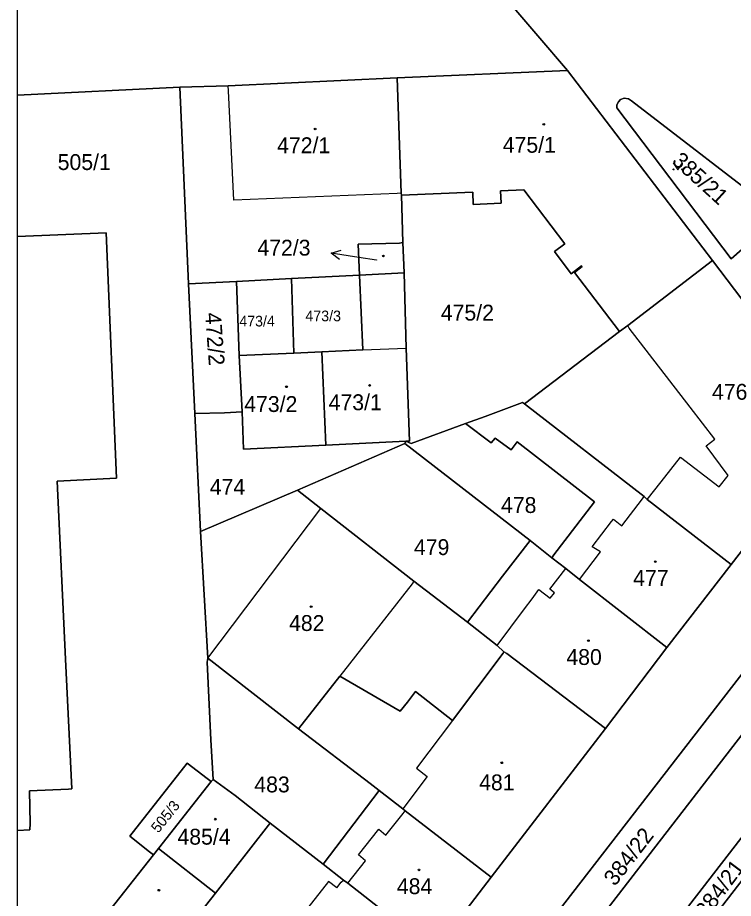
# Model space of a CAD drawing. Extents: x -598934 to -598196, y -1162208 to -1161502.
# Drawn here: x -598932 to -598855.4, y -1162110.9 to -1162016.6 of the extents above; entities that cross this region are included whole.
import ezdxf

# ---------------------------------------------------------------- set-up
doc = ezdxf.new("R2010")
doc.units = 0
for name, color, linetype in [('KN_CAR_KR', 7, 'Continuous'), ('KN_KULTURY', 7, 'Continuous'), ('KN_PARC_CIS_POM', 7, 'Continuous'), ('KN_PARC_CIS_POZ', 7, 'Continuous'), ('KN_PARC_CIS_STAV', 7, 'Continuous'), ('KN_PARC_PLOCHA', 7, 'Continuous'), ('PARC_C_SIPKA', 7, 'Continuous'), ('parcely_l', 7, 'Continuous')]:
    doc.layers.add(name, color=color, linetype=linetype)

msp = doc.modelspace()

# ---------------------------------------------------------------- linework, layer by layer
at = {"layer": 'KN_CAR_KR'}
for points in [[(-598909.44, -1162024.41), (-598909.46, -1162023.88)], [(-598908.86, -1162036.13), (-598909.44, -1162024.41)], [(-598891.37, -1162035.4), (-598908.86, -1162036.13)], [(-598890.96, -1162035.38), (-598891.37, -1162035.4)], [(-598866.55, -1162049.83), (-598866.7, -1162049.56)], [(-598860.03, -1162058.3), (-598866.55, -1162049.83)], [(-598895.07, -1162052.18), (-598890.43, -1162051.97)], [(-598857.38, -1162061.75), (-598860.03, -1162058.3)], [(-598858.3, -1162062.43), (-598857.38, -1162061.75)], [(-598855.94, -1162065.64), (-598858.3, -1162062.43)], [(-598863.13, -1162066.29), (-598861.06, -1162063.66)], [(-598861.06, -1162063.66), (-598856.91, -1162066.84)], [(-598856.91, -1162066.84), (-598855.94, -1162065.64)], [(-598864.6, -1162068.19), (-598863.13, -1162066.29)], [(-598865.12, -1162068.13), (-598864.95, -1162067.87)], [(-598867.33, -1162071.02), (-598865.12, -1162068.13)], [(-598911.67, -1162085.18), (-598899.56, -1162069.15)], [(-598870.52, -1162073.25), (-598868.43, -1162070.54)], [(-598868.43, -1162070.54), (-598868.23, -1162070.29)], [(-598868.23, -1162070.29), (-598867.33, -1162071.02)], [(-598869.61, -1162073.81), (-598870.52, -1162073.25)], [(-598871.87, -1162076.75), (-598869.61, -1162073.81)], [(-598875.04, -1162077.8), (-598873.32, -1162075.59)], [(-598889.78, -1162077.22), (-598897.51, -1162087.11)], [(-598889.59, -1162076.93), (-598889.78, -1162077.22)], [(-598876.92, -1162078.84), (-598876.23, -1162077.84)], [(-598876.23, -1162077.84), (-598875, -1162078.75)], [(-598874.53, -1162078.2), (-598875.04, -1162077.8)], [(-598875, -1162078.75), (-598874.53, -1162078.2)], [(-598877.75, -1162079.92), (-598876.92, -1162078.84)], [(-598880.69, -1162083.82), (-598877.75, -1162079.92)], [(-598885.45, -1162091.87), (-598889.3, -1162096.99)], [(-598889.3, -1162096.99), (-598888.17, -1162097.88)], [(-598888.17, -1162097.88), (-598890.78, -1162101.35)], [(-598892.6, -1162104.16), (-598890.73, -1162101.85)], [(-598890.73, -1162101.85), (-598890.53, -1162101.53)], [(-598895.51, -1162106.27), (-598893.34, -1162103.51)], [(-598893.34, -1162103.51), (-598892.6, -1162104.16)], [(-598894.78, -1162106.9), (-598895.51, -1162106.27)], [(-598896.68, -1162109.3), (-598894.78, -1162106.9)], [(-598898.72, -1162109.1), (-598903.31, -1162114.93)], [(-598897.85, -1162109.81), (-598898.72, -1162109.1)], [(-598897.85, -1162109.81), (-598897.39, -1162109.19)], [(-598897.39, -1162109.19), (-598897.13, -1162108.96)]]:
    msp.add_lwpolyline(points, dxfattribs=at)
at = {"layer": 'KN_KULTURY'}
msp.add_lwpolyline([(-598861.832, -1162032.132), (-598861.332, -1162032.882), (-598860.832, -1162032.132)], dxfattribs=at)
for centre, radius in [((-598875.69, -1162028.01), 0.09), ((-598875.69, -1162028.01), 0.0398), ((-598900.17, -1162028.5), 0.09), ((-598900.17, -1162028.5), 0.0398), ((-598861.782, -1162032.831), 0.05), ((-598860.883, -1162032.831), 0.05), ((-598892.86, -1162042.11), 0.09), ((-598892.86, -1162042.11), 0.0398), ((-598903.23, -1162056.12), 0.09), ((-598903.23, -1162056.12), 0.0398), ((-598894.33, -1162055.98), 0.09), ((-598894.33, -1162055.98), 0.0398), ((-598863.75, -1162074.85), 0.09), ((-598863.75, -1162074.85), 0.0398), ((-598900.59, -1162079.68), 0.09), ((-598900.59, -1162079.68), 0.0398), ((-598870.9, -1162083.32), 0.09), ((-598870.9, -1162083.32), 0.0398), ((-598880.18, -1162096.4), 0.09), ((-598880.18, -1162096.4), 0.0398), ((-598910.85, -1162102.44), 0.09), ((-598910.85, -1162102.44), 0.0398), ((-598889.05, -1162107.87), 0.09), ((-598889.05, -1162107.87), 0.0398), ((-598916.89, -1162110.05), 0.09), ((-598916.89, -1162110.05), 0.0398)]:
    msp.add_circle(centre, radius, dxfattribs=at)
at = {"layer": 'KN_PARC_PLOCHA'}
for points in [[(-598912.15, -1162007.46), (-598902.86, -1162008.29), (-598896.69, -1162008.84), (-598884.71, -1162008.72), (-598876.32, -1162018.53), (-598873.13, -1162022.24), (-598891.39, -1162023.04), (-598909.46, -1162023.88), (-598914.65, -1162024.03), (-598932.017, -1162024.888), (-598932.017, -1162008.017), (-598917.65, -1162007.34), (-598917.64, -1162007.83)], [(-598857.64, -1162042.61), (-598866.7, -1162049.56), (-598867.59, -1162050.19), (-598872.38, -1162043.88), (-598871.58, -1162043.24), (-598871.64, -1162043.17), (-598872.75, -1162044.01), (-598874.54, -1162041.63), (-598873.43, -1162040.8), (-598877.82, -1162035.02), (-598880.32, -1162035.13), (-598880.26, -1162036.45), (-598883.23, -1162036.58), (-598883.28, -1162035.26), (-598890.92, -1162035.59), (-598890.96, -1162035.38), (-598891.39, -1162023.04), (-598873.13, -1162022.24)], [(-598890.92, -1162035.59), (-598890.79, -1162040.67), (-598891.15, -1162040.72), (-598895.56, -1162040.86), (-598895.41, -1162044.15), (-598902.71, -1162044.53), (-598908.57, -1162044.84), (-598913.72, -1162045.11), (-598914.65, -1162024.03), (-598909.46, -1162023.88), (-598891.39, -1162023.04), (-598890.96, -1162035.38)], [(-598850.34, -1162037.79), (-598855.62, -1162042.42), (-598867.85, -1162026.24), (-598867.85, -1162025.92), (-598867.7, -1162025.58), (-598867.47, -1162025.35), (-598867.09, -1162025.2), (-598866.61, -1162025.27), (-598866.3, -1162025.49)], [(-598850.34, -1162037.79), (-598866.3, -1162025.49), (-598866.61, -1162025.27), (-598867.09, -1162025.2), (-598867.47, -1162025.35), (-598867.7, -1162025.58), (-598867.85, -1162025.92), (-598867.85, -1162026.24), (-598855.62, -1162042.42)], [(-598867.59, -1162050.19), (-598877.75, -1162057.95), (-598877.95, -1162057.8), (-598881.96, -1162059.32), (-598884.05, -1162060.07), (-598889.88, -1162062.18), (-598890.45, -1162061.95), (-598890.08, -1162061.93), (-598890.43, -1162051.97), (-598890.63, -1162043.9), (-598890.79, -1162040.67), (-598890.92, -1162035.59), (-598883.28, -1162035.26), (-598883.23, -1162036.58), (-598880.26, -1162036.45), (-598880.32, -1162035.13), (-598877.82, -1162035.02), (-598873.43, -1162040.8), (-598874.54, -1162041.63), (-598872.75, -1162044.01), (-598871.64, -1162043.17), (-598871.58, -1162043.24), (-598872.38, -1162043.88)], [(-598932.017, -1162103.669), (-598932.017, -1162040.025), (-598922.54, -1162039.63), (-598921.42, -1162065.9), (-598927.78, -1162066.24), (-598926.88, -1162085.29), (-598926.21, -1162099.2), (-598926.58, -1162099.22), (-598930.76, -1162099.41), (-598930.68, -1162102.91), (-598930.7, -1162103.6)], [(-598890.63, -1162043.9), (-598895.41, -1162044.15), (-598895.56, -1162040.86), (-598891.15, -1162040.72), (-598890.79, -1162040.67)], [(-598844.17, -1162060.34), (-598855.63, -1162075.16), (-598864.6, -1162068.19), (-598864.95, -1162067.87), (-598877.75, -1162057.95), (-598867.59, -1162050.19), (-598866.7, -1162049.56), (-598857.64, -1162042.61)], [(-598899.45, -1162052.38), (-598902.44, -1162052.51), (-598902.71, -1162044.53), (-598895.41, -1162044.15), (-598895.07, -1162052.18)], [(-598890.45, -1162061.95), (-598899.01, -1162062.37), (-598899.45, -1162052.38), (-598895.07, -1162052.18), (-598895.41, -1162044.15), (-598890.63, -1162043.9), (-598890.43, -1162051.97), (-598890.08, -1162061.93)], [(-598908.29, -1162052.77), (-598907.99, -1162058.8), (-598909.86, -1162058.92), (-598913.04, -1162059), (-598913.72, -1162045.11), (-598908.57, -1162044.84)], [(-598902.44, -1162052.51), (-598908.29, -1162052.77), (-598908.57, -1162044.84), (-598902.71, -1162044.53)], [(-598899.01, -1162062.37), (-598907.85, -1162062.81), (-598907.99, -1162058.8), (-598908.29, -1162052.77), (-598902.44, -1162052.51), (-598899.45, -1162052.38)], [(-598877.75, -1162057.95), (-598864.95, -1162067.87), (-598864.6, -1162068.19), (-598855.63, -1162075.16), (-598862.5, -1162084.05), (-598871.87, -1162076.75), (-598873.32, -1162075.59), (-598874.83, -1162074.43), (-598874.62, -1162074.13), (-598870.24, -1162068.44), (-598878.52, -1162062.01), (-598879.19, -1162062.88), (-598880.89, -1162061.64), (-598881.33, -1162062.14), (-598884.05, -1162060.07), (-598881.96, -1162059.32), (-598877.95, -1162057.8)], [(-598899.01, -1162062.37), (-598890.45, -1162061.95), (-598890.56, -1162062.18), (-598902.06, -1162067.19), (-598912.43, -1162071.62), (-598913.04, -1162059), (-598909.86, -1162058.92), (-598907.99, -1162058.8), (-598907.85, -1162062.81)], [(-598840.79, -1162062.93), (-598837.76, -1162065.26), (-598881.48, -1162121.83), (-598880.27, -1162122.81), (-598901.94, -1162150.79), (-598901.53, -1162151.13), (-598902.16, -1162151.9), (-598902.58, -1162151.62), (-598917.58, -1162171.02), (-598932.017, -1162189.781), (-598932.017, -1162174.389), (-598931.87, -1162174.2), (-598924.54, -1162164.69), (-598917.29, -1162155.14), (-598912.37, -1162148.88), (-598906.19, -1162140.84), (-598887.39, -1162116.58), (-598881.32, -1162108.67), (-598869.09, -1162092.74), (-598862.5, -1162084.05), (-598855.63, -1162075.16), (-598844.17, -1162060.34)], [(-598874.83, -1162074.43), (-598877.13, -1162072.6), (-598890.56, -1162062.18), (-598890.45, -1162061.95), (-598889.88, -1162062.18), (-598884.05, -1162060.07), (-598881.33, -1162062.14), (-598880.89, -1162061.64), (-598879.19, -1162062.88), (-598878.52, -1162062.01), (-598870.24, -1162068.44), (-598874.62, -1162074.13)], [(-598877.13, -1162072.6), (-598880.1, -1162076.42), (-598883.85, -1162081.33), (-598889.59, -1162076.93), (-598899.56, -1162069.15), (-598902.06, -1162067.19), (-598890.56, -1162062.18)], [(-598834.62, -1162067.66), (-598878.34, -1162124.34), (-598878.7, -1162124.05), (-598879.19, -1162123.66), (-598880.27, -1162122.81), (-598881.48, -1162121.83), (-598837.76, -1162065.26)], [(-598829.3, -1162071.75), (-598873.32, -1162128.74), (-598873, -1162128.98), (-598872.52, -1162129.34), (-598908.85, -1162176.37), (-598932.017, -1162206.357), (-598932.017, -1162192.125), (-598915.91, -1162171.29), (-598879.19, -1162123.66), (-598878.7, -1162124.05), (-598878.34, -1162124.34), (-598834.62, -1162067.66)], [(-598883.85, -1162081.33), (-598880.69, -1162083.82), (-598879.95, -1162084.5), (-598880.03, -1162084.66), (-598885.45, -1162091.87), (-598889.43, -1162088.77), (-598890.29, -1162089.91), (-598891.05, -1162090.87), (-598897.51, -1162087.11), (-598901.96, -1162092.78), (-598911.67, -1162085.18), (-598912.43, -1162071.62), (-598902.06, -1162067.19), (-598899.56, -1162069.15), (-598889.59, -1162076.93)], [(-598827.04, -1162073.49), (-598871.08, -1162130.49), (-598872.52, -1162129.34), (-598873, -1162128.98), (-598873.32, -1162128.74), (-598829.3, -1162071.75)], [(-598874.83, -1162074.43), (-598873.32, -1162075.59), (-598871.87, -1162076.75), (-598862.5, -1162084.05), (-598869.09, -1162092.74), (-598879.63, -1162084.69), (-598879.95, -1162084.5), (-598880.69, -1162083.82), (-598883.85, -1162081.33), (-598880.1, -1162076.42), (-598877.13, -1162072.6)], [(-598869.09, -1162092.74), (-598881.32, -1162108.67), (-598890.53, -1162101.53), (-598890.78, -1162101.35), (-598893.3, -1162099.38), (-598894.28, -1162098.61), (-598901.96, -1162092.78), (-598897.51, -1162087.11), (-598891.05, -1162090.87), (-598890.29, -1162089.91), (-598889.43, -1162088.77), (-598885.45, -1162091.87), (-598880.03, -1162084.66), (-598879.95, -1162084.5), (-598879.63, -1162084.69)], [(-598901.96, -1162092.78), (-598894.28, -1162098.61), (-598893.3, -1162099.38), (-598899.32, -1162107.25), (-598904.99, -1162102.88), (-598908.71, -1162099.92), (-598911.08, -1162098.18), (-598911.32, -1162093.95), (-598911.73, -1162085.63), (-598911.67, -1162085.18)], [(-598911.3, -1162098.39), (-598916.93, -1162105.58), (-598917.47, -1162106.27), (-598917.91, -1162105.93), (-598920, -1162104.26), (-598913.86, -1162096.45), (-598911.73, -1162098.09)], [(-598904.99, -1162102.88), (-598905.17, -1162103.07), (-598910.84, -1162110.36), (-598916.93, -1162105.58), (-598911.3, -1162098.39), (-598911.08, -1162098.18), (-598908.71, -1162099.92)], [(-598881.32, -1162108.67), (-598887.39, -1162116.58), (-598896.68, -1162109.3), (-598897.13, -1162108.96), (-598899.32, -1162107.25), (-598893.3, -1162099.38), (-598890.78, -1162101.35), (-598890.53, -1162101.53)], [(-598899.32, -1162107.25), (-598897.13, -1162108.96), (-598896.68, -1162109.3), (-598887.39, -1162116.58), (-598906.19, -1162140.84), (-598916.07, -1162133.24), (-598916.29, -1162133.03), (-598918.68, -1162131.12), (-598923.97, -1162127.06), (-598918.08, -1162119.58), (-598916.95, -1162120.45), (-598915.97, -1162119.19), (-598912.52, -1162114.78), (-598913.64, -1162113.95), (-598910.84, -1162110.36), (-598905.17, -1162103.07), (-598904.99, -1162102.88)], [(-598910.84, -1162110.36), (-598913.64, -1162113.95), (-598912.52, -1162114.78), (-598915.97, -1162119.19), (-598917.09, -1162118.32), (-598923.23, -1162113.54), (-598917.47, -1162106.27), (-598916.93, -1162105.58)]]:
    msp.add_lwpolyline(points, close=True, dxfattribs=at)
for points in [[(-598797.52, -1162010.97), (-598804.91, -1162020.57), (-598804.33, -1162021.01), (-598812.41, -1162031.47), (-598813, -1162031.05), (-598813.45, -1162031.95), (-598813.64, -1162032.95), (-598813.67, -1162034), (-598813.4, -1162035.12), (-598812.61, -1162036.32), (-598811.81, -1162037.05), (-598811.67, -1162037.16), (-598819.69, -1162047.55), (-598830.2, -1162061.93), (-598833.27, -1162059.45), (-598836.77, -1162056.74), (-598840.79, -1162062.93), (-598844.17, -1162060.34), (-598857.64, -1162042.61), (-598873.13, -1162022.24), (-598876.32, -1162018.53), (-598884.71, -1162008.72)], [(-598932.017, -1162124.67), (-598932.017, -1162103.669), (-598930.7, -1162103.6), (-598930.68, -1162102.91), (-598930.76, -1162099.41), (-598926.58, -1162099.22), (-598926.21, -1162099.2), (-598926.88, -1162085.29), (-598927.78, -1162066.24), (-598921.42, -1162065.9), (-598922.54, -1162039.63), (-598932.017, -1162040.025), (-598932.017, -1162024.888), (-598914.65, -1162024.03), (-598913.72, -1162045.11), (-598913.04, -1162059), (-598912.43, -1162071.62), (-598911.67, -1162085.18), (-598911.73, -1162085.63), (-598911.32, -1162093.95), (-598911.08, -1162098.18), (-598911.3, -1162098.39), (-598911.73, -1162098.09), (-598913.86, -1162096.45), (-598920, -1162104.26), (-598917.91, -1162105.93), (-598917.47, -1162106.27), (-598923.23, -1162113.54)], [(-598871.08, -1162130.49), (-598827.04, -1162073.49)]]:
    msp.add_lwpolyline(points, dxfattribs=at)
at = {"layer": 'PARC_C_SIPKA'}
for points in [[(-598897.543, -1162042.47), (-598898.455, -1162041.823), (-598897.391, -1162041.481)], [(-598893.61, -1162042.57), (-598895.49, -1162042.28), (-598898.455, -1162041.823)]]:
    msp.add_lwpolyline(points, dxfattribs=at)
at = {"layer": 'parcely_l'}
for points in [[(-598932.017, -1162024.888), (-598932.017, -1162008.017)], [(-598873.13, -1162022.24), (-598876.32, -1162018.53), (-598884.71, -1162008.72)], [(-598891.39, -1162023.04), (-598873.13, -1162022.24)], [(-598857.64, -1162042.61), (-598873.13, -1162022.24)], [(-598914.65, -1162024.03), (-598909.46, -1162023.88), (-598891.39, -1162023.04)], [(-598891.39, -1162023.04), (-598890.96, -1162035.38), (-598890.92, -1162035.59)], [(-598914.65, -1162024.03), (-598932.017, -1162024.888)], [(-598913.72, -1162045.11), (-598914.65, -1162024.03)], [(-598932.017, -1162040.025), (-598932.017, -1162024.888)], [(-598850.34, -1162037.79), (-598866.3, -1162025.49), (-598866.61, -1162025.27), (-598867.09, -1162025.2), (-598867.47, -1162025.35), (-598867.7, -1162025.58), (-598867.85, -1162025.92), (-598867.85, -1162026.24), (-598855.62, -1162042.42), (-598850.34, -1162037.79)], [(-598890.92, -1162035.59), (-598883.28, -1162035.26), (-598883.23, -1162036.58), (-598880.26, -1162036.45), (-598880.32, -1162035.13), (-598877.82, -1162035.02), (-598873.43, -1162040.8), (-598874.54, -1162041.63), (-598872.75, -1162044.01), (-598871.64, -1162043.17), (-598871.58, -1162043.24), (-598872.38, -1162043.88), (-598867.59, -1162050.19)], [(-598890.92, -1162035.59), (-598890.79, -1162040.67)], [(-598932.017, -1162040.025), (-598922.54, -1162039.63), (-598921.42, -1162065.9), (-598927.78, -1162066.24), (-598926.88, -1162085.29), (-598926.21, -1162099.2), (-598926.58, -1162099.22), (-598930.76, -1162099.41), (-598930.68, -1162102.91), (-598930.7, -1162103.6), (-598932.017, -1162103.669)], [(-598932.017, -1162103.669), (-598932.017, -1162040.025)], [(-598890.79, -1162040.67), (-598891.15, -1162040.72), (-598895.56, -1162040.86), (-598895.41, -1162044.15)], [(-598890.63, -1162043.9), (-598890.79, -1162040.67)], [(-598857.64, -1162042.61), (-598866.7, -1162049.56), (-598867.59, -1162050.19)], [(-598844.17, -1162060.34), (-598857.64, -1162042.61)], [(-598895.41, -1162044.15), (-598902.71, -1162044.53)], [(-598895.41, -1162044.15), (-598895.07, -1162052.18), (-598899.45, -1162052.38)], [(-598890.63, -1162043.9), (-598895.41, -1162044.15)], [(-598890.45, -1162061.95), (-598890.08, -1162061.93), (-598890.43, -1162051.97), (-598890.63, -1162043.9)], [(-598908.57, -1162044.84), (-598913.72, -1162045.11)], [(-598913.04, -1162059), (-598913.72, -1162045.11)], [(-598902.71, -1162044.53), (-598908.57, -1162044.84)], [(-598908.29, -1162052.77), (-598908.57, -1162044.84)], [(-598902.71, -1162044.53), (-598902.44, -1162052.51)], [(-598867.59, -1162050.19), (-598877.75, -1162057.95)], [(-598908.29, -1162052.77), (-598902.44, -1162052.51)], [(-598907.99, -1162058.8), (-598908.29, -1162052.77)], [(-598902.44, -1162052.51), (-598899.45, -1162052.38)], [(-598899.45, -1162052.38), (-598899.01, -1162062.37)], [(-598877.75, -1162057.95), (-598877.95, -1162057.8), (-598881.96, -1162059.32), (-598884.05, -1162060.07)], [(-598877.75, -1162057.95), (-598864.95, -1162067.87), (-598864.6, -1162068.19), (-598855.63, -1162075.16)], [(-598913.04, -1162059), (-598909.86, -1162058.92), (-598907.99, -1162058.8)], [(-598912.43, -1162071.62), (-598913.04, -1162059)], [(-598899.01, -1162062.37), (-598907.85, -1162062.81), (-598907.99, -1162058.8)], [(-598884.05, -1162060.07), (-598889.88, -1162062.18), (-598890.45, -1162061.95)], [(-598874.83, -1162074.43), (-598874.62, -1162074.13), (-598870.24, -1162068.44), (-598878.52, -1162062.01), (-598879.19, -1162062.88), (-598880.89, -1162061.64), (-598881.33, -1162062.14), (-598884.05, -1162060.07)], [(-598855.63, -1162075.16), (-598844.17, -1162060.34)], [(-598902.06, -1162067.19), (-598890.56, -1162062.18)], [(-598899.01, -1162062.37), (-598890.45, -1162061.95)], [(-598890.56, -1162062.18), (-598890.45, -1162061.95)], [(-598890.56, -1162062.18), (-598877.13, -1162072.6)], [(-598837.76, -1162065.26), (-598881.48, -1162121.83), (-598880.27, -1162122.81)], [(-598912.43, -1162071.62), (-598902.06, -1162067.19)], [(-598902.06, -1162067.19), (-598899.56, -1162069.15), (-598889.59, -1162076.93), (-598883.85, -1162081.33)], [(-598879.19, -1162123.66), (-598878.7, -1162124.05), (-598878.34, -1162124.34), (-598834.62, -1162067.66)], [(-598911.67, -1162085.18), (-598912.43, -1162071.62)], [(-598829.3, -1162071.75), (-598873.32, -1162128.74), (-598873, -1162128.98), (-598872.52, -1162129.34)], [(-598877.13, -1162072.6), (-598880.1, -1162076.42), (-598883.85, -1162081.33)], [(-598874.83, -1162074.43), (-598877.13, -1162072.6)], [(-598827.04, -1162073.49), (-598871.08, -1162130.49)], [(-598862.5, -1162084.05), (-598871.87, -1162076.75), (-598873.32, -1162075.59), (-598874.83, -1162074.43)], [(-598862.5, -1162084.05), (-598855.63, -1162075.16)], [(-598883.85, -1162081.33), (-598880.69, -1162083.82), (-598879.95, -1162084.5)], [(-598869.09, -1162092.74), (-598862.5, -1162084.05)], [(-598879.95, -1162084.5), (-598880.03, -1162084.66), (-598885.45, -1162091.87), (-598889.43, -1162088.77), (-598890.29, -1162089.91), (-598891.05, -1162090.87), (-598897.51, -1162087.11), (-598901.96, -1162092.78)], [(-598879.95, -1162084.5), (-598879.63, -1162084.69), (-598869.09, -1162092.74)], [(-598911.08, -1162098.18), (-598911.32, -1162093.95), (-598911.73, -1162085.63), (-598911.67, -1162085.18)], [(-598901.96, -1162092.78), (-598911.67, -1162085.18)], [(-598893.3, -1162099.38), (-598894.28, -1162098.61), (-598901.96, -1162092.78)], [(-598869.09, -1162092.74), (-598881.32, -1162108.67)], [(-598917.47, -1162106.27), (-598917.91, -1162105.93), (-598920, -1162104.26), (-598913.86, -1162096.45), (-598911.73, -1162098.09), (-598911.3, -1162098.39)], [(-598911.3, -1162098.39), (-598911.08, -1162098.18)], [(-598911.08, -1162098.18), (-598908.71, -1162099.92), (-598904.99, -1162102.88)], [(-598916.93, -1162105.58), (-598911.3, -1162098.39)], [(-598899.32, -1162107.25), (-598893.3, -1162099.38)], [(-598881.32, -1162108.67), (-598890.53, -1162101.53), (-598890.78, -1162101.35), (-598893.3, -1162099.38)], [(-598904.99, -1162102.88), (-598905.17, -1162103.07), (-598910.84, -1162110.36)], [(-598899.32, -1162107.25), (-598904.99, -1162102.88)], [(-598932.017, -1162124.67), (-598932.017, -1162103.669)], [(-598916.93, -1162105.58), (-598917.47, -1162106.27)], [(-598910.84, -1162110.36), (-598916.93, -1162105.58)], [(-598923.23, -1162113.54), (-598917.47, -1162106.27)], [(-598887.39, -1162116.58), (-598896.68, -1162109.3), (-598897.13, -1162108.96), (-598899.32, -1162107.25)], [(-598887.39, -1162116.58), (-598881.32, -1162108.67)], [(-598910.84, -1162110.36), (-598913.64, -1162113.95), (-598912.52, -1162114.78), (-598915.97, -1162119.19)]]:
    msp.add_lwpolyline(points, dxfattribs=at)

# ---------------------------------------------------------------- texts
at = {"layer": 'KN_PARC_CIS_POM'}
for s, height, p in [('505/1', 1.7, (-598927.727, -1162032.9)), ('472/3', 0.1, (-598893.843, -1162042.57))]:
    msp.add_text(s, height=height, dxfattribs=at).set_placement(p)
at = {"layer": 'KN_PARC_CIS_POZ'}
for s, height, rotation, p in [('385/21', 1.7, 317.69956, (-598862.066, -1162032.075)), ('472/2', 1.7, 274.22355, (-598911.952, -1162048.224)), ('505/3', 1.14, 51.29875, (-598916.953, -1162103.996)), ('384/22', 1.7, 52.2003, (-598868.069, -1162109.701)), ('384/21', 1.7, 53.10044, (-598858.271, -1162113.173))]:
    msp.add_text(s, height=height, rotation=rotation, dxfattribs=at).set_placement(p)
for s, height, p in [('475/2', 1.7, (-598886.712, -1162049.03)), ('473/3', 1.14, (-598901.21, -1162049.1)), ('473/4', 1.14, (-598908.29, -1162049.66)), ('474', 1.7, (-598911.447, -1162067.69)), ('478', 1.7, (-598880.267, -1162069.64)), ('479', 1.7, (-598889.587, -1162074.15)), ('483', 1.7, (-598906.677, -1162099.57))]:
    msp.add_text(s, height=height, dxfattribs=at).set_placement(p)
at = {"layer": 'KN_PARC_CIS_STAV'}
for s, p in [('472/1', (-598904.237, -1162031.1)), ('475/1', (-598880.077, -1162031.05)), ('472/3', (-598906.347, -1162042.07)), ('476', (-598857.677, -1162057.51)), ('473/2', (-598907.757, -1162058.82)), ('473/1', (-598898.717, -1162058.63)), ('477', (-598866.117, -1162077.45)), ('482', (-598902.957, -1162082.28)), ('480', (-598873.267, -1162085.92)), ('481', (-598882.607, -1162099.35)), ('485/4', (-598914.907, -1162105.17)), ('484', (-598891.417, -1162110.47))]:
    msp.add_text(s, height=1.7, dxfattribs=at).set_placement(p)

doc.saveas('drawing.dxf')
